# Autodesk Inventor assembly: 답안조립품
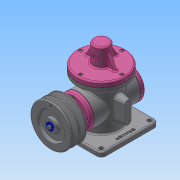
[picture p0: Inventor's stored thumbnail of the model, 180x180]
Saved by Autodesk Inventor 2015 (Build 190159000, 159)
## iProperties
Created: 2020-02
Part Number: 답안조립품
Document SubType Name: Assembly
Designer: user
Mass: 2562.84 g
Surface Area: 2485.59 cm^2
Volume: 789.817 cm^3
Density: 3.24486 g/cm^3
Author: user
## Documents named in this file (21)
- C:\Users\user\Desktop\600206V1028\답안조립품.iam
- C:\Users\user\Desktop\600206V1028\본체.ipt
- C:\Users\user\Desktop\600206V1028\베어링 17 x 40 x 12.ipt
- C:\Users\user\Desktop\600206V1028\개스킷 A.ipt
- C:\Users\user\Desktop\600206V1028\뒤커버.ipt
- C:\Users\user\Desktop\600206V1028\편심축.ipt
- C:\Users\user\Desktop\600206V1028\육각 소켓 머리 볼트 M4 x 10.ipt
- C:\Users\user\Desktop\600206V1028\키 4 x 4 x 25.ipt
- C:\Users\user\Desktop\600206V1028\앞커버.ipt
- C:\Users\user\Desktop\600206V1028\오일 실 17 30 8.ipt
- C:\Users\user\Desktop\600206V1028\V-벨트풀리.ipt
- C:\Users\user\Desktop\600206V1028\와셔 4x16.ipt
- C:\Users\user\Desktop\600206V1028\볼트 M4 x 10.ipt
- C:\Users\user\Desktop\600206V1028\링크.ipt
- C:\Users\user\Desktop\600206V1028\슬라이더.ipt
- C:\Users\user\Desktop\600206V1028\클레비스 핀 6 x 22.ipt
- 클레비스 핀 6 x 22.ipt
- C:\Users\user\Desktop\600206V1028\E-링.ipt
- C:\Users\user\Desktop\600206V1028\개스킷 B.ipt
- C:\Users\user\Desktop\600206V1028\덮개.ipt
- C:\Users\user\Desktop\600206V1028\가변스프링.ipt
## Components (6 placed, 5 different names)
1. 개스킷 A:1
2. 개스킷 A:2
3. V-벨트풀리:1
4. E-링:1
5. 개스킷 B:1
6. 가변스프링:1
